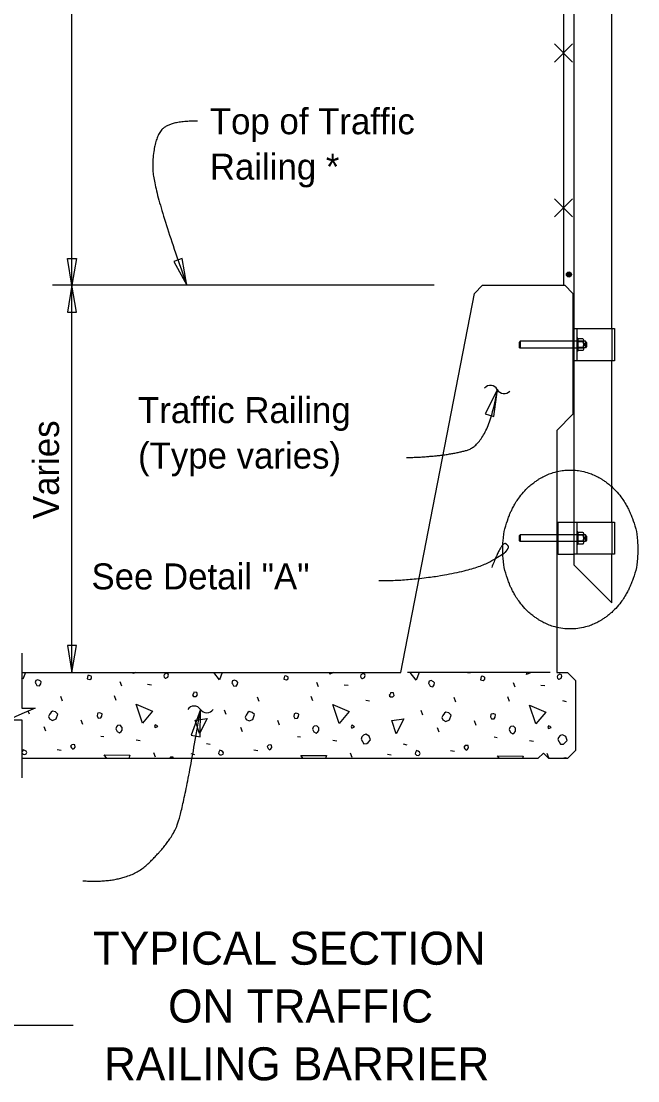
# Model space of a CAD drawing. Extents: x 0 to 72.1, y -15.2 to 30.1.
# Drawn here: x 29.03 to 33.81, y 13.11 to 21.32 of the extents above; entities that cross this region are included whole.
import ezdxf

# ---------------------------------------------------------------- set-up
doc = ezdxf.new("R2010")
doc.units = 0
for name, color, linetype in [('AdhocPoint_dp', 7, 'Continuous'), ('Border', 7, 'Continuous'), ('Patterning', 7, 'Continuous'), ('PlotBorder_dp', 7, 'Continuous'), ('SheetLines_dp', 7, 'Continuous'), ('SupstrConc_h', 7, 'Continuous'), ('TextMisc', 7, 'Continuous'), ('TrafBarrierConc', 7, 'Continuous')]:
    doc.layers.add(name, color=color, linetype=linetype)

msp = doc.modelspace()

# ---------------------------------------------------------------- linework, layer by layer
at = {"layer": 'AdhocPoint_dp'}
for p, q in [((29.0336, 16.2784), (31.9711, 16.2784)), ((33.1794, 16.2784), (33.2627, 16.2784)), ((33.2627, 16.2784), (33.3252, 16.2159)), ((33.3252, 16.2159), (33.3252, 15.6742)), ((33.0335, 15.6117), (29.0336, 15.6117)), ((33.0335, 15.6117), (33.0752, 15.6533)), ((33.0752, 15.6533), (33.1169, 15.6117)), ((33.2627, 15.6117), (33.1169, 15.6117)), ((33.3252, 15.6742), (33.2627, 15.6117))]:
    msp.add_line(p, q, dxfattribs=at)
at = {"layer": 'Border'}
for p, q in [((33.6065, 18.9432), (33.6065, 18.6932)), ((32.8959, 18.8443), (32.8878, 18.836)), ((32.8878, 18.836), (32.8878, 18.8004)), ((33.3891, 18.8443), (32.8959, 18.8443)), ((32.8959, 18.8443), (32.8959, 18.7922)), ((32.8959, 18.7922), (32.8878, 18.8004)), ((33.3891, 18.7922), (32.8959, 18.7922)), ((33.6065, 17.4432), (33.6065, 17.1932)), ((33.6065, 17.4432), (33.6065, 17.1932)), ((32.8959, 17.3443), (32.8878, 17.336)), ((32.8878, 17.336), (32.8878, 17.3004)), ((33.3891, 17.3443), (32.8959, 17.3443)), ((32.8959, 17.3443), (32.8959, 17.2922)), ((32.8959, 17.2922), (32.8878, 17.3004)), ((33.3891, 17.2922), (32.8959, 17.2922))]:
    msp.add_line(p, q, dxfattribs=at)
at = {"layer": 'Patterning'}
for p, q in [((33.3021, 21.149), (33.1607, 21.0078)), ((33.1607, 21.149), (33.3021, 21.0078)), ((33.3021, 19.949), (33.1607, 19.8078)), ((33.1607, 19.949), (33.3021, 19.8078)), ((33.3044, 18.9432), (33.3148, 18.9432)), ((33.3081, 18.9432), (33.3081, 18.6932)), ((33.3114, 18.9432), (33.3114, 18.6932)), ((33.3955, 18.8294), (33.3955, 18.8086)), ((33.4052, 18.8294), (33.4052, 18.8086)), ((33.3148, 18.6932), (33.3044, 18.6932)), ((33.1794, 17.4432), (33.1898, 17.4432)), ((33.1831, 17.4432), (33.1831, 17.1932)), ((33.1864, 17.4432), (33.1864, 17.1932)), ((33.3955, 17.3294), (33.3955, 17.3086)), ((33.4052, 17.3294), (33.4052, 17.3086)), ((33.1898, 17.1932), (33.1794, 17.1932)), ((30.9821, 16.2784), (30.9834, 16.2781)), ((32.4882, 16.2784), (32.5073, 16.2746)), ((29.8079, 16.1703), (29.7955, 16.2039)), ((30.0076, 16.1862), (30.0395, 16.1826)), ((31.3317, 16.1667), (31.3193, 16.2003)), ((31.5314, 16.1826), (31.5633, 16.1791)), ((32.8555, 16.1632), (32.8431, 16.1968)), ((33.0553, 16.1791), (33.0871, 16.1756)), ((29.7654, 16.0607), (29.7513, 16.096)), ((29.35, 16.0554), (29.3359, 16.0907)), ((30.8738, 16.0518), (30.8597, 16.0872)), ((31.2893, 16.0571), (31.2751, 16.0925)), ((31.6994, 16.0642), (31.7277, 16.0571)), ((32.3977, 16.0483), (32.3835, 16.0836)), ((32.8131, 16.0536), (32.7989, 16.0889)), ((33.2232, 16.0607), (33.2515, 16.0536)), ((29.0937, 15.9546), (29.0842, 15.9783)), ((30.6175, 15.9511), (30.6034, 15.9864)), ((32.1413, 15.9475), (32.1272, 15.9829)), ((29.2192, 15.822), (29.2068, 15.8556)), ((29.5074, 15.8733), (29.4932, 15.9086)), ((30.743, 15.8185), (30.7307, 15.8521)), ((31.0312, 15.8697), (31.017, 15.9051)), ((32.555, 15.8662), (32.5408, 15.9016)), ((29.6452, 15.7849), (29.67, 15.7814)), ((31.1691, 15.7814), (31.1938, 15.7778)), ((32.2668, 15.8149), (32.2545, 15.8485)), ((32.6929, 15.7778), (32.7176, 15.7743)), ((29.921, 15.7566), (29.9511, 15.7513)), ((30.4655, 15.7283), (30.4938, 15.7213)), ((31.4448, 15.7531), (31.4749, 15.7478)), ((31.9893, 15.7248), (32.0176, 15.7177)), ((32.9686, 15.7495), (32.9987, 15.7442)), ((29.3076, 15.6806), (29.3376, 15.6753)), ((30.0695, 15.6223), (30.0571, 15.6558)), ((30.3435, 15.6488), (30.3718, 15.6417)), ((30.8314, 15.6771), (30.8615, 15.6718)), ((31.5933, 15.6187), (31.5809, 15.6523)), ((31.8673, 15.6452), (31.8956, 15.6382)), ((32.3552, 15.6735), (32.3853, 15.6682)), ((33.1171, 15.6152), (33.1048, 15.6488))]:
    msp.add_line(p, q, dxfattribs=at)
for points in [[(33.2315, 25.2784), (33.2315, 19.2784)], [(29.0624, 16.2784), (29.0424, 16.2251)], [(29.8963, 16.2693), (29.8991, 16.2784)], [(29.9165, 16.2784), (29.8963, 16.2693)], [(30.1438, 16.2339), (30.1508, 16.2339), (30.165, 16.241), (30.1703, 16.2569), (30.1685, 16.2657), (30.1544, 16.2728), (30.1367, 16.2622), (30.1331, 16.2516), (30.1367, 16.241), (30.1438, 16.2339)], [(30.5662, 16.2215), (30.523, 16.2784)], [(30.5875, 16.2784), (30.5662, 16.2215)], [(31.4201, 16.2657), (31.424, 16.2784)], [(31.4482, 16.2784), (31.4201, 16.2657)], [(31.6676, 16.2304), (31.6746, 16.2304), (31.6888, 16.2374), (31.6941, 16.2534), (31.6923, 16.2622), (31.6782, 16.2693), (31.6605, 16.2587), (31.657, 16.248), (31.6605, 16.2374), (31.6676, 16.2304)], [(32.0901, 16.218), (32.0442, 16.2784)], [(32.1126, 16.2784), (32.0901, 16.218)], [(32.9439, 16.2622), (32.9489, 16.2784)], [(32.9799, 16.2784), (32.9439, 16.2622)], [(33.1914, 16.2268), (33.1985, 16.2268), (33.2126, 16.2339), (33.2179, 16.2498), (33.2161, 16.2587), (33.202, 16.2657), (33.1843, 16.2551), (33.1808, 16.2445), (33.1843, 16.2339), (33.1914, 16.2268)], [(29.0424, 16.2251), (29.0336, 16.2367)], [(29.1414, 16.1932), (29.1503, 16.1773), (29.1715, 16.1738), (29.1803, 16.1897), (29.1839, 16.2039), (29.175, 16.2127), (29.1591, 16.2215), (29.1432, 16.2162), (29.1379, 16.2003), (29.1414, 16.1932)], [(29.5409, 16.2286), (29.5604, 16.2233), (29.5728, 16.2321), (29.5745, 16.2445), (29.571, 16.248), (29.5569, 16.2551), (29.5445, 16.2534), (29.5427, 16.241), (29.5409, 16.2286)], [(30.6652, 16.1897), (30.6741, 16.1738), (30.6953, 16.1703), (30.7041, 16.1862), (30.7077, 16.2003), (30.6988, 16.2092), (30.6829, 16.218), (30.667, 16.2127), (30.6617, 16.1968), (30.6652, 16.1897)], [(31.0648, 16.2251), (31.0842, 16.2198), (31.0966, 16.2286), (31.0983, 16.241), (31.0948, 16.2445), (31.0807, 16.2516), (31.0683, 16.2498), (31.0665, 16.2374), (31.0648, 16.2251)], [(32.1891, 16.1862), (32.1979, 16.1703), (32.2191, 16.1667), (32.2279, 16.1826), (32.2315, 16.1968), (32.2226, 16.2056), (32.2067, 16.2145), (32.1908, 16.2092), (32.1855, 16.1932), (32.1891, 16.1862)], [(32.5886, 16.2215), (32.608, 16.2162), (32.6204, 16.2251), (32.6222, 16.2374), (32.6186, 16.241), (32.6045, 16.248), (32.5921, 16.2463), (32.5903, 16.2339), (32.5886, 16.2215)], [(30.363, 16.0925), (30.3842, 16.0925), (30.3948, 16.1031), (30.3895, 16.1225), (30.3665, 16.1243), (30.363, 16.1137), (30.3577, 16.1049), (30.363, 16.0925), (30.3594, 16.096)], [(31.8868, 16.0889), (31.908, 16.0889), (31.9186, 16.0996), (31.9133, 16.119), (31.8903, 16.1208), (31.8868, 16.1102), (31.8815, 16.1013), (31.8868, 16.0889), (31.8832, 16.0925)], [(29.9687, 15.8857), (29.921, 16.0324), (30.0465, 15.9776), (29.9687, 15.8857)], [(31.4926, 15.8821), (31.4448, 16.0288), (31.5703, 15.974), (31.4926, 15.8821)], [(33.0164, 15.8786), (32.9686, 16.0253), (33.0942, 15.9705), (33.0164, 15.8786)], [(29.2475, 15.9175), (29.2705, 15.9051), (29.3005, 15.9175), (29.3129, 15.9546), (29.2952, 15.9723), (29.2722, 15.9776), (29.2616, 15.9705), (29.2493, 15.9511), (29.2404, 15.9352), (29.2475, 15.9175)], [(29.617, 15.9405), (29.6258, 15.9245), (29.6452, 15.9263), (29.6541, 15.9387), (29.6558, 15.9581), (29.6435, 15.9634), (29.6346, 15.9652), (29.624, 15.9617), (29.6205, 15.9581), (29.617, 15.9405)], [(30.7713, 15.9139), (30.7943, 15.9016), (30.8243, 15.9139), (30.8367, 15.9511), (30.819, 15.9687), (30.7961, 15.974), (30.7855, 15.967), (30.7731, 15.9475), (30.7642, 15.9316), (30.7713, 15.9139)], [(31.1408, 15.9369), (31.1496, 15.921), (31.1691, 15.9228), (31.1779, 15.9352), (31.1797, 15.9546), (31.1673, 15.9599), (31.1584, 15.9617), (31.1478, 15.9581), (31.1443, 15.9546), (31.1408, 15.9369)], [(32.2951, 15.9104), (32.3181, 15.898), (32.3482, 15.9104), (32.3605, 15.9475), (32.3429, 15.9652), (32.3199, 15.9705), (32.3093, 15.9634), (32.2969, 15.944), (32.2881, 15.9281), (32.2951, 15.9104)], [(32.6646, 15.9334), (32.6734, 15.9175), (32.6929, 15.9192), (32.7017, 15.9316), (32.7035, 15.9511), (32.6911, 15.9564), (32.6823, 15.9581), (32.6717, 15.9546), (32.6681, 15.9511), (32.6646, 15.9334)], [(29.7619, 15.8415), (29.7725, 15.8202), (29.7902, 15.8096), (29.8043, 15.8202), (29.8114, 15.8309), (29.8114, 15.8521), (29.7955, 15.868), (29.7761, 15.8662), (29.7672, 15.8574), (29.7619, 15.8415)], [(30.0677, 15.8503), (30.0872, 15.8591), (30.0801, 15.8662), (30.0677, 15.8715), (30.0624, 15.8591), (30.0677, 15.8503)], [(30.4107, 15.8043), (30.3771, 15.9086), (30.4708, 15.921), (30.4107, 15.8043)], [(31.2857, 15.8379), (31.2963, 15.8167), (31.314, 15.8061), (31.3282, 15.8167), (31.3352, 15.8273), (31.3352, 15.8485), (31.3193, 15.8644), (31.2999, 15.8627), (31.291, 15.8538), (31.2857, 15.8379)], [(31.5916, 15.8468), (31.611, 15.8556), (31.6039, 15.8627), (31.5916, 15.868), (31.5862, 15.8556), (31.5916, 15.8468)], [(31.9345, 15.8008), (31.9009, 15.9051), (31.9946, 15.9175), (31.9345, 15.8008)], [(32.8095, 15.8344), (32.8202, 15.8132), (32.8378, 15.8026), (32.852, 15.8132), (32.859, 15.8238), (32.859, 15.845), (32.8431, 15.8609), (32.8237, 15.8591), (32.8148, 15.8503), (32.8095, 15.8344)], [(33.1154, 15.8432), (33.1348, 15.8521), (33.1277, 15.8591), (33.1154, 15.8644), (33.1101, 15.8521), (33.1154, 15.8432)], [(31.6623, 15.7619), (31.6852, 15.7248), (31.7082, 15.7266), (31.7171, 15.7354), (31.7365, 15.7548), (31.7241, 15.7849), (31.6994, 15.799), (31.6817, 15.792), (31.6676, 15.7778), (31.6623, 15.7619)], [(33.1861, 15.7584), (33.2091, 15.7213), (33.232, 15.723), (33.2409, 15.7319), (33.2603, 15.7513), (33.248, 15.7814), (33.2232, 15.7955), (33.2055, 15.7884), (33.1914, 15.7743), (33.1861, 15.7584)], [(29.419, 15.693), (29.4296, 15.6824), (29.4402, 15.6894), (29.4473, 15.7), (29.4437, 15.7177), (29.4349, 15.7195), (29.4225, 15.7177), (29.4119, 15.7071), (29.419, 15.693)], [(30.9428, 15.6894), (30.9534, 15.6788), (30.964, 15.6859), (30.9711, 15.6965), (30.9675, 15.7142), (30.9587, 15.716), (30.9463, 15.7142), (30.9357, 15.7036), (30.9428, 15.6894)], [(32.4666, 15.6859), (32.4772, 15.6753), (32.4878, 15.6824), (32.4949, 15.693), (32.4913, 15.7106), (32.4825, 15.7124), (32.4701, 15.7106), (32.4595, 15.7), (32.4666, 15.6859)], [(29.0442, 15.6435), (29.0566, 15.6417), (29.0689, 15.647), (29.0725, 15.6576), (29.0672, 15.6665), (29.0566, 15.6735), (29.0442, 15.6788), (29.0371, 15.6647), (29.0336, 15.6541)], [(29.0336, 15.6541), (29.0442, 15.6435)], [(29.6919, 15.6117), (29.6718, 15.6382), (29.8715, 15.6364), (29.8623, 15.6117)], [(30.2092, 15.6116), (30.2074, 15.6208), (30.1985, 15.6225), (30.1861, 15.6208), (30.177, 15.6116)], [(30.568, 15.6399), (30.5804, 15.6382), (30.5928, 15.6435), (30.5963, 15.6541), (30.591, 15.6629), (30.5804, 15.67), (30.568, 15.6753), (30.5609, 15.6611), (30.5574, 15.6505), (30.568, 15.6399)], [(31.213, 15.6117), (31.1956, 15.6346), (31.3953, 15.6329), (31.3874, 15.6117)], [(32.0918, 15.6364), (32.1042, 15.6346), (32.1166, 15.6399), (32.1201, 15.6505), (32.1148, 15.6594), (32.1042, 15.6665), (32.0918, 15.6718), (32.0848, 15.6576), (32.0812, 15.647), (32.0918, 15.6364)], [(32.7342, 15.6117), (32.7194, 15.6311), (32.9191, 15.6293), (32.9125, 15.6117)], [(33.2554, 15.6116), (33.255, 15.6137), (33.2461, 15.6155), (33.2338, 15.6137), (33.2317, 15.6116)]]:
    msp.add_lwpolyline(points, dxfattribs=at)
at = {"layer": 'PlotBorder_dp'}
for p, q in [((29.4221, 16.2784), (29.4221, 25.2784)), ((32.23, 19.2784), (29.2721, 19.2784)), ((23.6311, 13.5439), (29.4313, 13.5439))]:
    msp.add_line(p, q, dxfattribs=at)
for points in [[(29.4221, 19.2784), (29.3868, 19.4866), (29.4574, 19.4866)], [(30.3137, 19.2784), (30.2776, 19.4865), (30.2111, 19.463)], [(29.4221, 19.2784), (29.3868, 19.0701), (29.4574, 19.0701)], [(32.7186, 18.4705), (32.6245, 18.2814), (32.692, 18.2609)], [(29.4221, 16.2784), (29.4574, 16.4866), (29.3868, 16.4866)], [(30.419, 15.9908), (30.3472, 15.7922), (30.4166, 15.7796)]]:
    msp.add_lwpolyline(points, close=True, dxfattribs=at)
msp.add_lwpolyline([(29.0336, 16.4284), (29.0336, 16.0012), (29.1369, 16.0012), (29.0336, 15.9563), (28.9303, 15.9113), (29.0336, 15.9113), (29.0336, 15.4617)], dxfattribs=at)
for centre, start, end in [((32.6649, 18.4432), 27.32823, 139.05545), ((32.7708, 18.498), 207.32823, 319.05545), ((30.3687, 15.9576), 33.91896, 145.64618), ((30.4677, 16.0241), 213.91896, 325.64618)]:
    msp.add_arc(centre, 0.0596, start, end, dxfattribs=at)
for points, degree in [([(30.3962, 20.5498), (30.1544, 20.5557), (30.0482, 20.3668), (30.0482, 20.0125), (30.3136, 19.2784)], 2), ([(32.0143, 17.9428), (32.3119, 17.9515), (32.6483, 18.0468), (32.7186, 18.4704)], 2), ([(33.2838, 16.6146), (33.3188, 16.6146), (33.3535, 16.6188), (33.4214, 16.6349), (33.4546, 16.6469), (33.5024, 16.6705), (33.518, 16.6793), (33.5408, 16.6938), (33.5483, 16.6989), (33.5631, 16.7095), (33.5703, 16.715), (33.606, 16.7434), (33.6323, 16.7693), (33.6802, 16.8264), (33.7017, 16.8576), (33.7251, 16.8995), (33.7296, 16.908), (33.7383, 16.9253), (33.7425, 16.9341), (33.7544, 16.9608), (33.7616, 16.9789), (33.7936, 17.0713), (33.8069, 17.1504), (33.8069, 17.3107), (33.7936, 17.3898), (33.7616, 17.4822), (33.7544, 17.5003), (33.7425, 17.5269), (33.7383, 17.5357), (33.7296, 17.553), (33.7251, 17.5615), (33.7017, 17.6034), (33.6802, 17.6347), (33.6323, 17.6918), (33.606, 17.7177), (33.5703, 17.7461), (33.5631, 17.7516), (33.5483, 17.7621), (33.5408, 17.7672), (33.518, 17.7818), (33.5024, 17.7906), (33.4546, 17.8142), (33.4214, 17.8262), (33.3535, 17.8423), (33.3188, 17.8464), (33.2488, 17.8464), (33.2141, 17.8423), (33.1461, 17.8262), (33.113, 17.8142), (33.0652, 17.7906), (33.0496, 17.7818), (33.0268, 17.7672), (33.0193, 17.7621), (33.0045, 17.7516), (32.9973, 17.7461), (32.9616, 17.7177), (32.9353, 17.6918), (32.8874, 17.6347), (32.8659, 17.6034), (32.8425, 17.5615), (32.8379, 17.553), (32.8292, 17.5357), (32.8251, 17.5269), (32.8132, 17.5003), (32.806, 17.4822), (32.7739, 17.3898), (32.7607, 17.3107), (32.7607, 17.1504), (32.7739, 17.0713), (32.806, 16.9789), (32.8132, 16.9608), (32.8251, 16.9341), (32.8292, 16.9253), (32.8379, 16.908), (32.8425, 16.8995), (32.8659, 16.8576), (32.8874, 16.8264), (32.9353, 16.7693), (32.9616, 16.7434), (32.9973, 16.715), (33.0045, 16.7095), (33.0193, 16.6989), (33.0268, 16.6938), (33.0496, 16.6793), (33.0652, 16.6705), (33.113, 16.6469), (33.1461, 16.6349), (33.2141, 16.6188), (33.2488, 16.6146), (33.2838, 16.6146)], 3), ([(31.801, 16.991), (32.0236, 16.9864), (32.5603, 17.0763), (32.7853, 17.2085), (32.796, 17.2305), (32.8122, 17.2564), (32.753, 17.2941), (32.6749, 17.0899)], 2), ([(29.5076, 14.6632), (29.8533, 14.6399), (30.1769, 14.9552), (30.2848, 15.1974), (30.419, 15.9912)], 2)]:
    msp.add_open_spline(points, degree=degree, dxfattribs=at)
at = {"layer": 'SupstrConc_h'}
msp.add_line((33.1284, 16.2784), (32.0221, 16.2784), dxfattribs=at)
at = {"layer": 'TextMisc'}
for p, q in [((33.2315, 25.2784), (33.2315, 19.2784)), ((33.3148, 18.9432), (33.3148, 25.2784)), ((33.6065, 18.9432), (33.6065, 25.2784)), ((33.3148, 18.6932), (33.3148, 18.9432)), ((33.3148, 18.9432), (33.6273, 18.9432)), ((33.3357, 18.9432), (33.3357, 18.6932)), ((33.6273, 18.9432), (33.6273, 18.6932)), ((33.3428, 18.8679), (33.3357, 18.8679)), ((33.3428, 18.8679), (33.3428, 18.7685)), ((33.3804, 18.8636), (33.3428, 18.8636)), ((33.3428, 18.7729), (33.3428, 18.8636)), ((33.3807, 18.8409), (33.3428, 18.8409)), ((33.3891, 18.7842), (33.3891, 18.8523)), ((33.4004, 18.844), (33.3891, 18.844)), ((33.4004, 18.844), (33.4004, 18.7925)), ((33.4101, 18.8343), (33.4004, 18.844)), ((33.4101, 18.8343), (33.4101, 18.8038)), ((33.3428, 18.7685), (33.3357, 18.7685)), ((33.3807, 18.7956), (33.3428, 18.7956)), ((33.3804, 18.7729), (33.3428, 18.7729)), ((33.4004, 18.7925), (33.3891, 18.7925)), ((33.4101, 18.8038), (33.4004, 18.7925)), ((33.3148, 17.1099), (33.3148, 18.6932)), ((33.6273, 18.6932), (33.3148, 18.6932)), ((33.6065, 17.4432), (33.6065, 18.6932)), ((33.1898, 17.1932), (33.1898, 17.4432)), ((33.1898, 17.4432), (33.3148, 17.4432)), ((33.3148, 17.4432), (33.6273, 17.4432)), ((33.3357, 17.4432), (33.3357, 17.1932)), ((33.6273, 17.4432), (33.6273, 17.1932)), ((33.3428, 17.3679), (33.3357, 17.3679)), ((33.3428, 17.3679), (33.3428, 17.2685)), ((33.3804, 17.3636), (33.3428, 17.3636)), ((33.3428, 17.2729), (33.3428, 17.3636)), ((33.3807, 17.3409), (33.3428, 17.3409)), ((33.3891, 17.2842), (33.3891, 17.3523)), ((33.4004, 17.344), (33.3891, 17.344)), ((33.4004, 17.344), (33.4004, 17.2925)), ((33.4101, 17.3343), (33.4004, 17.344)), ((33.4101, 17.3343), (33.4101, 17.3038)), ((33.3428, 17.2685), (33.3357, 17.2685)), ((33.3807, 17.2956), (33.3428, 17.2956)), ((33.3804, 17.2729), (33.3428, 17.2729)), ((33.4004, 17.2925), (33.3891, 17.2925)), ((33.4101, 17.3038), (33.4004, 17.2925)), ((33.1898, 17.1932), (33.3148, 17.1932)), ((33.6273, 17.1932), (33.3148, 17.1932)), ((33.6065, 16.8182), (33.6065, 17.1932))]:
    msp.add_line(p, q, dxfattribs=at)
msp.add_lwpolyline([(33.3148, 17.1099), (33.6065, 16.8182)], dxfattribs=at)
for radius in [0.0197, 0.0172, 0.0147, 0.0122, 0.00975, 0.00725, 0.00475, 0.00225]:
    msp.add_circle((33.2732, 19.3617), radius, dxfattribs=at)
for centre, radius, start, end in [((33.3773, 18.8522), 0.0118, 286.59863, 74.70054), ((33.3544, 18.8182), 0.0347, 319.20147, 40.79853), ((33.3774, 18.7842), 0.0118, 285.15064, 73.50417), ((33.3773, 17.3522), 0.0118, 286.59863, 74.70054), ((33.3544, 17.3182), 0.0347, 319.20147, 40.79853), ((33.3774, 17.2842), 0.0118, 285.15064, 73.50417)]:
    msp.add_arc(centre, radius, start, end, dxfattribs=at)
at = {"layer": 'TrafBarrierConc'}
for p, q in [((32.5404, 19.2158), (32.6029, 19.2783)), ((32.6029, 19.2783), (33.2419, 19.2784)), ((33.2419, 19.2783), (33.3044, 19.2158)), ((31.9711, 16.2784), (32.5404, 19.2158)), ((33.3044, 19.2158), (33.3044, 18.2783)), ((33.3044, 18.2783), (33.1794, 18.1533)), ((33.1794, 18.1533), (33.1794, 16.2784))]:
    msp.add_line(p, q, dxfattribs=at)

# ---------------------------------------------------------------- texts
at = {"layer": 'PlotBorder_dp'}
for s, height, p in [('Top of Traffic ', 0.2016, (30.4907, 20.4488)), ('Railing *', 0.2016, (30.4907, 20.0968)), ('Traffic Railing ', 0.2016, (29.9344, 18.21)), ('(Type varies)', 0.2016, (29.9344, 17.858)), ('TYPICAL SECTION', 0.256001, (29.5843, 14.0127)), ('ON TRAFFIC', 0.256, (30.1671, 13.5647)), ('RAILING BARRIER', 0.256001, (29.6705, 13.1167))]:
    msp.add_text(s, height=height, dxfattribs=at).set_placement(p)
at = {"layer": 'SheetLines_dp'}
msp.add_text('Varies', height=0.2016, rotation=90, dxfattribs=at).set_placement((29.3221, 17.4665))
msp.add_text('See Detail "A"', height=0.2016, dxfattribs=at).set_placement((29.5735, 16.9215))

doc.saveas('drawing.dxf')
